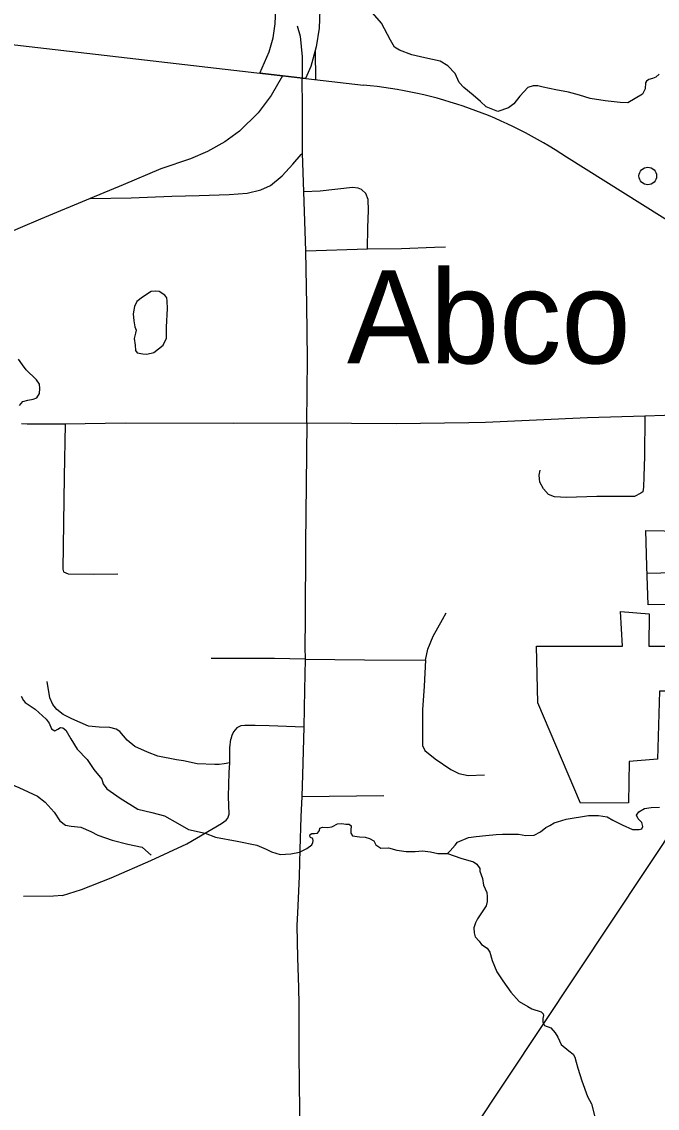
# Model space of a CAD drawing. Extents: x 22866 to 28196, y 1324810 to 1328105.
# Drawn here: x 25739.1 to 25825.7, y 1325934.5 to 1326082.4 of the extents above; entities that cross this region are included whole.
import ezdxf

# ---------------------------------------------------------------- set-up
doc = ezdxf.new("R2010")
doc.units = 0
for name, color, linetype in [('Level 15', 7, 'Continuous'), ('Level 24', 7, 'Continuous'), ('Level 31', 7, 'Continuous'), ('Level 32', 7, 'Continuous'), ('Level 33', 7, 'Continuous'), ('Level 35', 7, 'Continuous'), ('Level 46', 7, 'Continuous'), ('Level 56', 7, 'Continuous'), ('Level 6', 7, 'Continuous'), ('Level 63', 7, 'Continuous')]:
    doc.layers.add(name, color=color, linetype=linetype)

msp = doc.modelspace()

# ---------------------------------------------------------------- linework, layer by layer
at = {"layer": 'Level 15'}
msp.add_line((25777.8, 1326074.67), (25771.56, 1326075.39), dxfattribs=at)
for points in [[(25771.56, 1326075.39), (25772.86, 1326078.33), (25773.38, 1326080.23), (25773.67, 1326082.13), (25773.76, 1326084.22), (25773.86, 1326090.11), (25773.86, 1326100.2), (25773.82, 1326106.29), (25779.82, 1326106.32)], [(25779.82, 1326106.32), (25779.86, 1326100.21), (25779.86, 1326090.06), (25779.76, 1326084.04), (25779.66, 1326081.55), (25779.26, 1326078.98), (25778.53, 1326076.31), (25777.8, 1326074.67)], [(25774.66, 1326075.03), (25773.11, 1326072.35), (25771.32, 1326070.02), (25768.79, 1326067.53), (25766.79, 1326066.07), (25764.46, 1326064.76), (25762.12, 1326063.74)], [(25762.12, 1326063.74), (25758.09, 1326062.4), (25752.94, 1326060.21), (25748.46, 1326058.36), (25741.71, 1326055.53), (25738.91, 1326054.35), (25731.29, 1326051.15), (25725.77, 1326048.85), (25722.46, 1326047.29), (25719.11, 1326045.24), (25716.87, 1326043.44), (25713.81, 1326041.11), (25709.28, 1326037.31), (25705.2, 1326034.1), (25699.9, 1326029.86), (25693.43, 1326024.51), (25692.08, 1326023.41), (25690.33, 1326021.66), (25689.06, 1326020.1), (25688.74, 1326019.52)], [(25762.12, 1326063.74), (25758.09, 1326062.4), (25752.94, 1326060.21), (25748.46, 1326058.36), (25741.71, 1326055.53), (25738.91, 1326054.35)]]:
    msp.add_lwpolyline(points, dxfattribs=at)
at = {"layer": 'Level 31'}
for points in [[(25776.66, 1326081.84), (25777.08, 1326080.45), (25777.32, 1326077.61), (25777.34, 1326074.72)], [(25779.12, 1326078.46), (25779.14, 1326074.52)], [(25777.98, 1326027.76), (25778.08, 1326036.47), (25777.95, 1326043.84), (25777.84, 1326051.22), (25777.57, 1326059.25), (25777.36, 1326064.52), (25777.36, 1326066.77), (25777.36, 1326070.72), (25777.34, 1326074.72)], [(25748.46, 1326058.36), (25754.06, 1326058.44), (25759.59, 1326058.65), (25763.29, 1326058.75), (25767.37, 1326058.89), (25769.82, 1326059.06), (25771.72, 1326059.51), (25773.04, 1326060.1), (25774.59, 1326061.42), (25776.08, 1326063.01), (25777.18, 1326064.32), (25777.36, 1326064.52)], [(25786.21, 1326051.5), (25786.27, 1326054.4), (25786.38, 1326056.69), (25786.31, 1326058.21), (25786, 1326059.04), (25785.41, 1326059.56), (25784.96, 1326059.73), (25784.2, 1326059.83), (25779.78, 1326059.35), (25777.57, 1326059.25)], [(25777.84, 1326051.22), (25786.21, 1326051.5), (25790.87, 1326051.53), (25795.36, 1326051.74), (25796.85, 1326051.77)], [(25777.98, 1326027.76), (25767.98, 1326027.73), (25753.24, 1326027.76), (25745.06, 1326027.61), (25740.23, 1326027.61)], [(25777.98, 1326027.76), (25777.86, 1326019.45), (25777.77, 1326011.31), (25777.73, 1326001.04), (25777.7, 1325997.28), (25777.74, 1325995.65)], [(25823.99, 1326028.73), (25816.18, 1326028.48), (25802.32, 1326027.83), (25800.02, 1326027.79), (25790.15, 1326027.69), (25777.98, 1326027.76)], [(25841.36, 1326028.97), (25830.62, 1326028.91), (25829.16, 1326028.87), (25826.66, 1326028.79), (25823.99, 1326028.73)], [(25794.11, 1325995.51), (25794.44, 1325996.98), (25795.17, 1325998.74), (25796.45, 1326001.05), (25796.93, 1326001.96)], [(25777.74, 1325995.65), (25773.55, 1325995.71), (25768.11, 1325995.74), (25764.95, 1325995.74)], [(25777.74, 1325995.65), (25777.65, 1325991.47), (25777.55, 1325986.35), (25777.37, 1325979.88), (25777.27, 1325976.95), (25777.15, 1325974.18), (25777.02, 1325969.71), (25776.93, 1325966.1), (25776.78, 1325963.06), (25776.68, 1325961.1), (25776.62, 1325959.38), (25776.68, 1325954.97), (25776.84, 1325950.93), (25776.87, 1325948.6), (25776.9, 1325941.78), (25776.96, 1325934.17), (25776.81, 1325926.85), (25776.87, 1325920.33), (25776.68, 1325916.56), (25776.68, 1325915.01), (25776.9, 1325910.63)], [(25777.74, 1325995.65), (25785.8, 1325995.56), (25794.11, 1325995.51)], [(25794.11, 1325995.51), (25793.96, 1325991.97), (25793.74, 1325988.75), (25793.7, 1325985.15), (25793.74, 1325983.87), (25794.03, 1325983.18), (25795.46, 1325982.04), (25797.59, 1325980.61), (25798.68, 1325980.06), (25799.93, 1325979.77), (25802.16, 1325979.88)], [(25777.55, 1325986.35), (25772.86, 1325986.57), (25770.95, 1325986.6), (25769.54, 1325986.6), (25769, 1325986.55), (25768.45, 1325986.27), (25767.99, 1325985.74), (25767.77, 1325985.25), (25767.6, 1325984.74)], [(25767.4, 1325980.2), (25767.48, 1325981.53), (25767.49, 1325983.58), (25767.6, 1325984.74)], [(25760.23, 1325981.91), (25757.67, 1325982.43), (25756.26, 1325982.97)], [(25766.01, 1325981.29), (25765.42, 1325981.29), (25763.04, 1325981.36), (25761.18, 1325981.77), (25760.23, 1325981.91)], [(25767.48, 1325981.53), (25766.71, 1325981.4), (25766.01, 1325981.29)], [(25766.35, 1325973.26), (25766.96, 1325973.73), (25767.22, 1325974), (25767.37, 1325974.53), (25767.29, 1325976.95), (25767.4, 1325980.2)], [(25744.71, 1325963.47), (25747.27, 1325964.28), (25751.33, 1325965.85), (25756.72, 1325968.24), (25761.62, 1325970.51), (25766.35, 1325973.26)], [(25744.71, 1325963.47), (25743.45, 1325963.37), (25739.37, 1325963.34)]]:
    msp.add_lwpolyline(points, dxfattribs=at)
at = {"layer": 'Level 32'}
for points in [[(25745.06, 1326027.61), (25744.91, 1326020.43), (25744.76, 1326007.88)], [(25823.99, 1326028.73), (25823.96, 1326023.25), (25823.87, 1326020.51), (25823.81, 1326019.05), (25823.72, 1326018.43), (25823.47, 1326018.21), (25822.57, 1326017.78), (25817.44, 1326017.78), (25813.34, 1326017.65), (25811.7, 1326017.71), (25810.89, 1326018.06), (25810.18, 1326018.83), (25809.68, 1326019.73), (25809.65, 1326020.2), (25809.59, 1326020.7), (25809.74, 1326021.35)], [(25744.76, 1326007.88), (25744.84, 1326007.54), (25745.47, 1326007.26), (25748.91, 1326007.2), (25752.23, 1326007.23)], [(25748.25, 1325986.49), (25747.09, 1325987), (25745.96, 1325987.51), (25744.78, 1325988.1), (25743.94, 1325988.76), (25743.39, 1325989.46), (25742.95, 1325990.37), (25742.59, 1325992.61)], [(25756.26, 1325982.97), (25754.55, 1325983.75), (25753.49, 1325984.59), (25752.5, 1325985.76), (25751.99, 1325986.09), (25751.15, 1325986.31), (25749.68, 1325986.35), (25748.25, 1325986.49)], [(25777.27, 1325976.95), (25788.46, 1325977.07)]]:
    msp.add_lwpolyline(points, dxfattribs=at)
at = {"layer": 'Level 33'}
msp.add_lwpolyline([(25841.24, 1326007.61), (25833.55, 1326007.52), (25824.33, 1326007.28)], dxfattribs=at)
at = {"layer": 'Level 35'}
for points in [[(25790.57, 1326078.55), (25789.89, 1326078.95), (25789.37, 1326079.89), (25788.12, 1326082.2), (25786.91, 1326083.61), (25785.4, 1326085.02), (25784.25, 1326086.07), (25783.72, 1326086.07), (25782.78, 1326085.6), (25781.53, 1326084.86), (25779.78, 1326084.95)], [(25825.93, 1326075.27), (25825.49, 1326074.86), (25825.02, 1326074.67), (25824.52, 1326074.54), (25824.21, 1326074.33), (25824.07, 1326074.07), (25824.05, 1326073.29), (25823.66, 1326072.55), (25822.66, 1326071.98), (25821.67, 1326071.35), (25820.65, 1326071.4), (25818.59, 1326071.64), (25816.55, 1326071.95), (25815.11, 1326072.4), (25813.62, 1326072.84), (25811.87, 1326073.16), (25810.17, 1326073.52), (25809.44, 1326073.7), (25808.81, 1326073.68), (25808.08, 1326073.47), (25806.98, 1326072.29), (25806.14, 1326071.25), (25805.41, 1326070.67), (25803.97, 1326070.17), (25803.53, 1326070.38), (25802.41, 1326070.83), (25801.62, 1326071.56), (25800.63, 1326072.42), (25799.37, 1326073.44), (25798.72, 1326074.15), (25798.17, 1326075.35), (25797.15, 1326076.4), (25796.13, 1326077.05), (25794.04, 1326077.5), (25792.26, 1326077.92), (25790.57, 1326078.55)], [(25756.17, 1326037.16), (25757.14, 1326037.37), (25758.42, 1326038.4), (25758.87, 1326039.34), (25758.87, 1326040.82), (25758.97, 1326043.35), (25758.94, 1326044.35), (25758.9, 1326044.84), (25758.63, 1326045.18), (25757.87, 1326045.67), (25757.42, 1326045.74), (25756.79, 1326045.67), (25755.58, 1326044.91), (25754.82, 1326044.32), (25754.48, 1326043.66), (25754.31, 1326042.66), (25754.41, 1326041.69), (25754.55, 1326040.89), (25754.72, 1326040.44), (25754.65, 1326039.99), (25754.44, 1326039.27), (25754.58, 1326038.37), (25754.65, 1326037.64), (25754.86, 1326037.33), (25755.64, 1326037.18)], [(25755.64, 1326037.18), (25756.17, 1326037.16)], [(25739.05, 1325990.61), (25739.36, 1325989.98), (25739.63, 1325989.72), (25740.96, 1325988.8), (25742.47, 1325987.44), (25742.89, 1325986.92), (25743.21, 1325986.14), (25743.65, 1325985.87), (25744.07, 1325986.08), (25744.43, 1325986.34), (25744.72, 1325986.29), (25745.14, 1325985.95), (25745.85, 1325984.77), (25746.68, 1325983.36), (25748.07, 1325981.98), (25748.96, 1325980.61), (25750.03, 1325979.31)], [(25732.23, 1325987), (25733.69, 1325985.44), (25734.55, 1325984.06), (25735.34, 1325982.17), (25736.07, 1325980.19), (25736.46, 1325979.3), (25736.78, 1325978.96), (25738.76, 1325978.17), (25741.3, 1325976.99), (25742.34, 1325976.18), (25743.55, 1325974.82), (25744.33, 1325973.62), (25745.09, 1325973.02), (25745.87, 1325972.89), (25747.18, 1325972.78), (25748.56, 1325972.15), (25749.51, 1325971.68), (25751.47, 1325970.98), (25753.61, 1325970.43), (25755.52, 1325970.03), (25756.01, 1325969.62), (25756.79, 1325968.96)], [(25750.03, 1325979.31), (25750.23, 1325978.67), (25750.73, 1325977.99), (25752.56, 1325976.71), (25754.96, 1325975.19), (25756.87, 1325974.77), (25758.57, 1325974.3), (25760.37, 1325973.28), (25761.86, 1325972.44), (25764.11, 1325971.92), (25765.55, 1325971.4), (25768.5, 1325970.85), (25771.17, 1325970.3), (25772.45, 1325969.75), (25773.17, 1325969.39), (25774.32, 1325969.03), (25775.81, 1325969.13), (25776.98, 1325969.34), (25777.98, 1325969.84), (25778.63, 1325970.36), (25778.79, 1325970.67), (25778.84, 1325970.88), (25778.79, 1325971.2), (25778.45, 1325971.33), (25778.37, 1325971.51), (25778.4, 1325971.75), (25778.63, 1325971.9), (25779, 1325971.88), (25779.44, 1325971.93), (25779.68, 1325972.3), (25779.76, 1325972.61), (25780.1, 1325972.74), (25780.8, 1325972.69), (25781.38, 1325972.79), (25781.48, 1325972.84), (25782.16, 1325973.21), (25782.74, 1325973.24), (25783.26, 1325973.18), (25783.72, 1325973.16), (25784.02, 1325972.95)], [(25813.28, 1325973.84), (25816.34, 1325974.33), (25817.7, 1325974.35), (25818.87, 1325974.15), (25819.63, 1325973.73), (25820.91, 1325973.07), (25822.32, 1325972.42), (25823.21, 1325972.44), (25823.6, 1325972.55), (25823.73, 1325972.86), (25823.6, 1325973.41), (25823.11, 1325973.91), (25822.84, 1325974.38), (25823.16, 1325974.83), (25823.94, 1325975.32), (25824.88, 1325975.43), (25826.01, 1325975.48)], [(25784.02, 1325972.95), (25783.98, 1325972.37), (25783.98, 1325971.93), (25784.19, 1325971.56), (25785.13, 1325971.46), (25785.89, 1325971.41), (25786.52, 1325971.2), (25787.07, 1325970.91), (25787.38, 1325970.33), (25788.06, 1325969.91), (25789.11, 1325969.94), (25790.23, 1325969.63), (25791.49, 1325969.44), (25792.71, 1325969.44), (25793.71, 1325969.52), (25794.83, 1325969.39), (25795.83, 1325969.16), (25797.11, 1325969.16)], [(25797.11, 1325969.16), (25797.49, 1325969.55), (25798.15, 1325970.31), (25798.49, 1325970.73), (25799.98, 1325971.35), (25801.02, 1325971.48), (25802.33, 1325971.64), (25803.74, 1325971.77), (25804.63, 1325971.82), (25805.73, 1325971.8), (25806.8, 1325971.82), (25807.79, 1325971.64), (25808.94, 1325971.67), (25809.8, 1325972.11), (25810.51, 1325972.69), (25811.06, 1325973), (25811.66, 1325973.34), (25812.1, 1325973.47), (25812.71, 1325973.66), (25813.28, 1325973.84)], [(25797.11, 1325969.16), (25798.93, 1325968.56), (25800.66, 1325968.04), (25801.1, 1325967.7), (25801.54, 1325967.12), (25801.54, 1325966.78), (25801.88, 1325965.79), (25802.01, 1325964.87), (25802.46, 1325963.88), (25802.51, 1325963.33), (25802.51, 1325962.62), (25802.41, 1325962.05), (25801.75, 1325961.08), (25801.2, 1325960.29), (25800.92, 1325959.75), (25800.73, 1325959.06), (25800.76, 1325958.38), (25800.89, 1325957.84), (25801.44, 1325957.23), (25801.75, 1325956.79)], [(25801.75, 1325956.79), (25802.51, 1325956.28), (25802.9, 1325955.76), (25803.22, 1325954.61), (25803.82, 1325953.04), (25804.65, 1325951.86), (25805.73, 1325950.29), (25806.9, 1325949.01), (25808.05, 1325948.33), (25808.63, 1325948.04), (25809.88, 1325947.6), (25810.14, 1325947.35), (25810.19, 1325947.14), (25810.11, 1325946.7), (25810.09, 1325946.22), (25810.32, 1325945.75), (25811.21, 1325945.44), (25811.79, 1325944.76), (25812.13, 1325944.16), (25812.62, 1325943.19), (25813.67, 1325942.3), (25814.22, 1325941.86), (25814.45, 1325941.44), (25814.64, 1325940.78), (25814.87, 1325939.95), (25815.42, 1325938.22), (25816.21, 1325936.1), (25816.73, 1325935.11), (25817.17, 1325933.3)]]:
    msp.add_lwpolyline(points, dxfattribs=at)
at = {"layer": 'Level 46'}
for points in [[(25738.84, 1326030.16), (25739.3, 1326030.69), (25739.99, 1326030.9), (25740.7, 1326031.03), (25741.2, 1326031.21), (25741.57, 1326031.81), (25741.6, 1326032.46), (25741.54, 1326033.08), (25741.17, 1326033.67), (25740.67, 1326034.14), (25740.2, 1326034.57), (25739.74, 1326035.04), (25739.24, 1326035.69), (25738.71, 1326036.47)], [(25740.23, 1326027.61), (25739.86, 1326027.61), (25739.12, 1326027.67)]]:
    msp.add_lwpolyline(points, dxfattribs=at)
at = {"layer": 'Level 56'}
msp.add_circle((25824.4, 1326061.41), 1.2, dxfattribs=at)
at = {"layer": 'Level 6'}
msp.add_lwpolyline([(25836.62, 1325985.43), (25836.69, 1325986.92), (25833.72, 1325986.92), (25833.69, 1325991.29), (25826.01, 1325991.26), (25825.7, 1325982.02), (25821.86, 1325981.71), (25821.77, 1325976.08), (25815.25, 1325976.02), (25809.44, 1325989.67), (25809.26, 1325997.41), (25820.97, 1325997.41), (25820.7, 1326002.1), (25824.59, 1326001.78), (25824.52, 1325997.4), (25836.46, 1325997.4), (25836.41, 1326003.14), (25824.47, 1326003.03), (25824.29, 1326008.28), (25824.13, 1326013.13), (25829.11, 1326013.07), (25829.29, 1326008.17), (25829.43, 1326008.16)], dxfattribs=at)
at = {"layer": 'Level 63'}
for p, q in [((25698.38, 1326083.84), (25785.68, 1326073.76)), ((25835.82, 1326049.88), (25813.34, 1326063.95)), ((25763.43, 1325875.59), (25845.35, 1325998.89))]:
    msp.add_line(p, q, dxfattribs=at)
msp.add_arc((25780.45, 1326015.16), 58.84, 56.0203, 84.902, dxfattribs=at)

# ---------------------------------------------------------------- texts
at = {"layer": 'Level 24'}
msp.add_text('Abco', height=12.674, dxfattribs=at).set_placement((25783.43, 1326035.89))

doc.saveas('drawing.dxf')
